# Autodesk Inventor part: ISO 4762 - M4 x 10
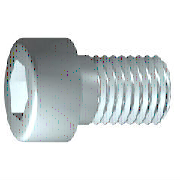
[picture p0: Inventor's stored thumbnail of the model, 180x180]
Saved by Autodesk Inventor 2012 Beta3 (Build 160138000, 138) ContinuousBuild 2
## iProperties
Created: 2010-02
Part Number: ISO 4762 - M4 x 10
Material: Stainless Steel, 440C
Description: Hexagon Socket Head Cap Screw
Document SubType Name: Modeling
Standard: ISO 4762
Designer: Thom Tremblay
Standard Revision: Fourth edition 2004-03-01
Standards Organization: ISO
Language: en-US
Size Designation: M4 x 10
Categories: <MemberInstance><Categories><Category DisplayName="Fasteners" InternalName="e4da775c-781d-43d5-af7c-5136215cf5a6" Mnemonic="FSTN"><Category DisplayName="Bolts"
Density: 7.75 g/cm^3
IsCustomPart: 0
Author: Thom Tremblay
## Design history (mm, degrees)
body "Solid1"
workplane "Work Plane1"
fillet "Fillet2" dims "d30" = 0.1 (= R)
revolve "Body" stored, may be unused: angle "d10" = 90 deg
sketch "Sketch2"
  geometry: L1 (0, -4.9)-(0, 4.9) reference; L2 (-4.9, 0)-(4.9, 0) reference; L3 (1.732, 0)-(0.866, -1.5); L4 (0.866, -1.5)-(-0.866, -1.5); L5 (-0.866, -1.5)-(-1.732, 0); L6 (-1.732, 0)-(-0.866, 1.5); L7 (-0.866, 1.5)-(0.866, 1.5); L8 (0.866, 1.5)-(1.732, 0); 2 further points
  constraints: 12 end point, 1 coincident, 1 horizontal alignment, 1 point on line, 12 other
extrude "Slot" join sketch "Sketch2" stored distance "d11" = 10; taper "d12" = 0 deg
fillet "Fillet1" dims "d17" = 0.4 (= RR)
feature "Thread" dims "d13" = 8.25 (= GEL), "d14" = 0
chamfer "Chamfer1" distance "d15" = 0.42941 (= -0.5 x SPD + 0.5 x GD); stored, may be unused: second distance "d16" = 0.42941 (= GUL), angle "d27" = 45 deg
sketch "Sketch1"
  geometry: L1 (-1, 0)-(10, 0); L2 (10, 0)-(10, 2); L3 (10, 2)-(1.75, 2); L4 (1.75, 2)-(1.32, 2); L5 (1.32, 2)-(0, 2); L6 (0, 2)-(0, 3.5); L7 (0, 3.5)-(-4, 3.5); L8 (-4, 3.5)-(-4, 1.732); L9 (-4, 1.732)-(-2, 1.732); L10 (-2, 1.732)-(-1, 0); L11 (-6.8, 0)-(12.8, 0) reference; L12 (0, -0.7)-(0, 4.2) reference; L13 (1.75, 2)-(0, 2)
  constraints: 22 end point, 6 parallel, 2 collinear, 2 perpendicular, 1 horizontal, 1 point on line
  dimensions: "d1" = 8.25 distance from line of L3.end L2 (= GEL); "d2" = 0.42952 distance of L4.end L3.end (computed from GAL); "d3" = 4 distance between parallel lines of L8 L6 (= KOH); "d4" = 2 distance of L8.end L9.end (= INTI); "d5" = 60 deg angle of L10 L1; "d6" = 4 diameter of L3 L1 (= GD); "d7" = 4 diameter of L5 L1 (= BDM); "d8" = 3.4641 diameter of L9 L1 (= 1.1547 x SW); "d9" = 7 diameter of L7 L1 (= KOD); "d26" = 10 distance between parallel lines of L12 L2 (= NLG)
other parameters: "GD" = 4 [user parameter; used in 2 equation terms], "NLG" = 10 [user parameter; used in 1 equation term], "GEL" = 8.25 [user parameter; used in 2 equation terms], "KOD" = 7 [user parameter; used in 1 equation term], "KOH" = 4 [user parameter; used in 1 equation term], "INTI" = 2 [user parameter; used in 1 equation term], "GAL" = 0.42941 (= 0.61345 x PTC) [user parameter; used in 1 equation term], "GUL" = 0.42941 (= 0.61345 x PTC) [user parameter; used in 1 equation term], "BDM" = 4 (= NND) [user parameter; used in 1 equation term], "SW" = 3 [user parameter; used in 2 equation terms], "RR" = 0.4 [user parameter; used in 1 equation term], "SPD" = 3.14117 (= NND - 1.2269 x PTC) [user parameter; used in 1 equation term], "d19" = 0, "d28" = 0, "d29" = 0, "R" = 0.1 [user parameter; used in 1 equation term], "TOA" = 30 deg [user parameter], "GD1" = 3.14117 (= THREADDIA - 1.2269 x PTC) [user parameter], "THREADDIA" = 4 [user parameter; used in 1 equation term], "FAWI" = 45 deg [user parameter], "TPU" = 14.28571 (computed from PTC) [user parameter], "PTC" = 0.7 [user parameter; used in 5 equation terms], "NND" = 4 [user parameter; used in 2 equation terms], "E0" = 3.465 (= 1.155 x SW) [user parameter]
